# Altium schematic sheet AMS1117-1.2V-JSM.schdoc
size 127 x 101 mm
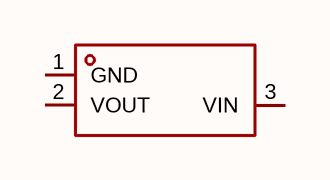
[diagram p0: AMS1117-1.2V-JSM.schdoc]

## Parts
U?  ams1117-1.2v-jsm  [SOT-89-3_L4.5-W2.4-P1.50-LS4.0-BR]  (value not drawn)

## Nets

Not connected (* = marked no-connect by the designer): U? 1(GND) 2(VOUT) 3(VIN)

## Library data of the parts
U? = ams1117-1.2v-jsm: 输出极性:正极;工作电压:15V;输出电压:1.2V;输出电流:1.2A;电源纹波抑制比(PSRR):-;输出类型:固定;; Manufacturer: JSMSEMI(杰盛微); AddInBom: yes; ModelId: dde435042bae4b9691e74da94cf9d9f3; ModelTransform: 177.165,161.417,0,90,0,0,-2.323,0,0; Output Configuration: 正极; Voltage - Supply: 15V; Output Voltage: 1.2V; Output Current: 1.2A; Voltage Dropout: 1.3V@(800mA); standby current: 2mA; Output Type: 固定; Number of Outputs: 1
